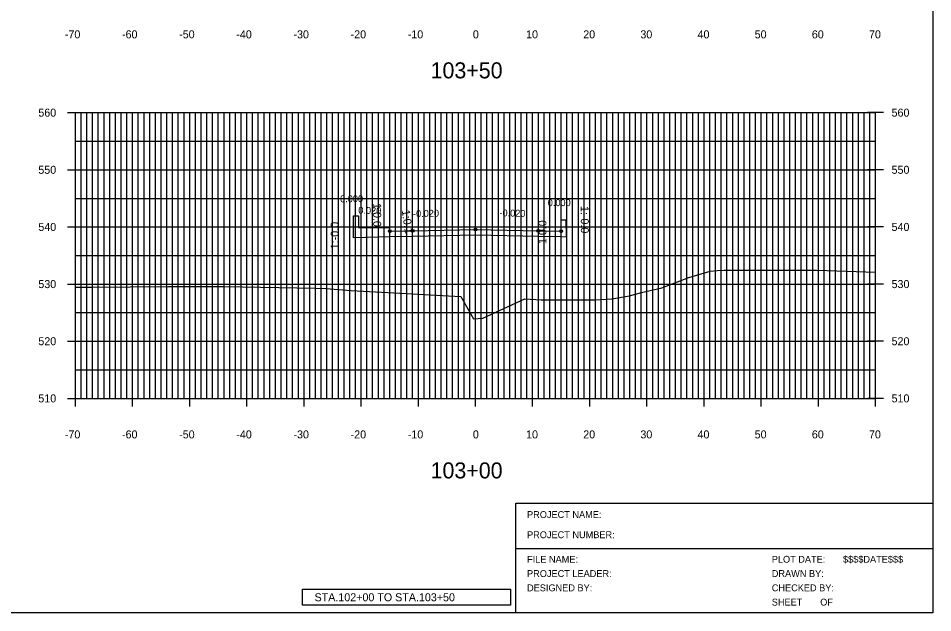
# Model space of a CAD drawing. Extents: x 1509063 to 1512863, y 401160 to 402918.
# Drawn here: x 1511622.7 to 1511782.7, y 402252.1 to 402356.1 of the extents above; entities that cross this region are included whole.
import ezdxf

# ---------------------------------------------------------------- set-up
doc = ezdxf.new("R2010")
doc.units = 0
for name, color, linetype in [('NBL1', 7, 'Continuous'), ('PET_P', 7, 'Continuous'), ('PRC', 7, 'Continuous'), ('PSP_P', 7, 'Continuous'), ('XAX_P', 7, 'Continuous'), ('XAXTIC_P', 7, 'Continuous'), ('XAXTXT_P_T', 7, 'Continuous'), ('XFRAME_P', 7, 'Continuous'), ('XGL_P', 7, 'Continuous'), ('XSL1_P', 7, 'Continuous'), ('XSL1_P_T', 7, 'Continuous'), ('XSL3_P', 7, 'Continuous'), ('XSLOG', 7, 'Continuous')]:
    doc.layers.add(name, color=color, linetype=linetype)

msp = doc.modelspace()

# ---------------------------------------------------------------- linework, layer by layer
at = {"layer": 'NBL1'}
for p, q in [((1511709.81, 402271.25), (1511782.73, 402271.25)), ((1511709.81, 402252.08), (1511709.81, 402271.25)), ((1511709.81, 402263.33), (1511782.73, 402263.33))]:
    msp.add_line(p, q, dxfattribs=at)
msp.add_lwpolyline([(1511782.73, 402252.08), (1511462.73, 402252.08), (1511462.73, 402462.08), (1511782.73, 402462.08)], close=True, dxfattribs=at)
at = {"layer": 'PET_P'}
for centre in [(1511691.73, 402318.9), (1511713.73, 402318.9)]:
    msp.add_circle(centre, 0.25, dxfattribs=at)
at = {"layer": 'PRC'}
msp.add_circle((1511702.73, 402319.12), 0.25, dxfattribs=at)
at = {"layer": 'PSP_P'}
for centre in [(1511687.73, 402318.82), (1511717.73, 402318.82)]:
    msp.add_circle(centre, 0.25, dxfattribs=at)
at = {"layer": 'XAX_P'}
for p, q in [((1511632.73, 402289.58), (1511632.73, 402339.58)), ((1511702.73, 402289.58), (1511702.73, 402339.58)), ((1511772.73, 402289.58), (1511772.73, 402339.58)), ((1511632.73, 402289.58), (1511772.73, 402289.58))]:
    msp.add_line(p, q, dxfattribs=at)
at = {"layer": 'XAXTIC_P'}
for p, q in [((1511631.33, 402339.58), (1511634.13, 402339.58)), ((1511701.33, 402339.58), (1511704.13, 402339.58)), ((1511774.13, 402339.58), (1511771.33, 402339.58)), ((1511631.33, 402329.58), (1511634.13, 402329.58)), ((1511701.33, 402329.58), (1511704.13, 402329.58)), ((1511774.13, 402329.58), (1511771.33, 402329.58)), ((1511631.33, 402319.58), (1511634.13, 402319.58)), ((1511701.33, 402319.58), (1511704.13, 402319.58)), ((1511774.13, 402319.58), (1511771.33, 402319.58)), ((1511631.33, 402309.58), (1511634.13, 402309.58)), ((1511701.33, 402309.58), (1511704.13, 402309.58)), ((1511774.13, 402309.58), (1511771.33, 402309.58)), ((1511631.33, 402299.58), (1511634.13, 402299.58)), ((1511701.33, 402299.58), (1511704.13, 402299.58)), ((1511774.13, 402299.58), (1511771.33, 402299.58)), ((1511632.73, 402288.18), (1511632.73, 402290.98)), ((1511642.73, 402288.18), (1511642.73, 402290.98)), ((1511652.73, 402288.18), (1511652.73, 402290.98)), ((1511662.73, 402288.18), (1511662.73, 402290.98)), ((1511672.73, 402288.18), (1511672.73, 402290.98)), ((1511682.73, 402288.18), (1511682.73, 402290.98)), ((1511692.73, 402288.18), (1511692.73, 402290.98)), ((1511702.73, 402288.18), (1511702.73, 402290.98)), ((1511712.73, 402288.18), (1511712.73, 402290.98)), ((1511722.73, 402288.18), (1511722.73, 402290.98)), ((1511732.73, 402288.18), (1511732.73, 402290.98)), ((1511742.73, 402288.18), (1511742.73, 402290.98)), ((1511752.73, 402288.18), (1511752.73, 402290.98)), ((1511762.73, 402288.18), (1511762.73, 402290.98)), ((1511772.73, 402288.18), (1511772.73, 402290.98)), ((1511631.33, 402289.58), (1511634.13, 402289.58)), ((1511701.33, 402289.58), (1511704.13, 402289.58)), ((1511774.13, 402289.58), (1511771.33, 402289.58))]:
    msp.add_line(p, q, dxfattribs=at)
at = {"layer": 'XFRAME_P'}
msp.add_lwpolyline([(1511672.43, 402256.18), (1511708.83, 402256.18), (1511708.83, 402253.38), (1511672.43, 402253.38)], close=True, dxfattribs=at)
at = {"layer": 'XGL_P'}
for p, q in [((1511632.73, 402339.58), (1511772.73, 402339.58)), ((1511632.73, 402289.58), (1511632.73, 402339.58)), ((1511633.73, 402289.58), (1511633.73, 402339.58)), ((1511634.73, 402289.58), (1511634.73, 402339.58)), ((1511635.73, 402289.58), (1511635.73, 402339.58)), ((1511636.73, 402289.58), (1511636.73, 402339.58)), ((1511637.73, 402289.58), (1511637.73, 402339.58)), ((1511638.73, 402289.58), (1511638.73, 402339.58)), ((1511639.73, 402289.58), (1511639.73, 402339.58)), ((1511640.73, 402289.58), (1511640.73, 402339.58)), ((1511641.73, 402289.58), (1511641.73, 402339.58)), ((1511642.73, 402289.58), (1511642.73, 402339.58)), ((1511643.73, 402289.58), (1511643.73, 402339.58)), ((1511644.73, 402289.58), (1511644.73, 402339.58)), ((1511645.73, 402289.58), (1511645.73, 402339.58)), ((1511646.73, 402289.58), (1511646.73, 402339.58)), ((1511647.73, 402289.58), (1511647.73, 402339.58)), ((1511648.73, 402289.58), (1511648.73, 402339.58)), ((1511649.73, 402289.58), (1511649.73, 402339.58)), ((1511650.73, 402289.58), (1511650.73, 402339.58)), ((1511651.73, 402289.58), (1511651.73, 402339.58)), ((1511652.73, 402289.58), (1511652.73, 402339.58)), ((1511653.73, 402289.58), (1511653.73, 402339.58)), ((1511654.73, 402289.58), (1511654.73, 402339.58)), ((1511655.73, 402289.58), (1511655.73, 402339.58)), ((1511656.73, 402289.58), (1511656.73, 402339.58)), ((1511657.73, 402289.58), (1511657.73, 402339.58)), ((1511658.73, 402289.58), (1511658.73, 402339.58)), ((1511659.73, 402289.58), (1511659.73, 402339.58)), ((1511660.73, 402289.58), (1511660.73, 402339.58)), ((1511661.73, 402289.58), (1511661.73, 402339.58)), ((1511662.73, 402289.58), (1511662.73, 402339.58)), ((1511663.73, 402289.58), (1511663.73, 402339.58)), ((1511664.73, 402289.58), (1511664.73, 402339.58)), ((1511665.73, 402289.58), (1511665.73, 402339.58)), ((1511666.73, 402289.58), (1511666.73, 402339.58)), ((1511667.73, 402289.58), (1511667.73, 402339.58)), ((1511668.73, 402289.58), (1511668.73, 402339.58)), ((1511669.73, 402289.58), (1511669.73, 402339.58)), ((1511670.73, 402289.58), (1511670.73, 402339.58)), ((1511671.73, 402289.58), (1511671.73, 402339.58)), ((1511672.73, 402289.58), (1511672.73, 402339.58)), ((1511673.73, 402289.58), (1511673.73, 402339.58)), ((1511674.73, 402289.58), (1511674.73, 402339.58)), ((1511675.73, 402289.58), (1511675.73, 402339.58)), ((1511676.73, 402289.58), (1511676.73, 402339.58)), ((1511677.73, 402289.58), (1511677.73, 402339.58)), ((1511678.73, 402289.58), (1511678.73, 402339.58)), ((1511679.73, 402289.58), (1511679.73, 402339.58)), ((1511680.73, 402289.58), (1511680.73, 402339.58)), ((1511681.73, 402289.58), (1511681.73, 402339.58)), ((1511682.73, 402289.58), (1511682.73, 402339.58)), ((1511683.73, 402289.58), (1511683.73, 402339.58)), ((1511684.73, 402289.58), (1511684.73, 402339.58)), ((1511685.73, 402289.58), (1511685.73, 402339.58)), ((1511686.73, 402289.58), (1511686.73, 402339.58)), ((1511687.73, 402289.58), (1511687.73, 402339.58)), ((1511688.73, 402289.58), (1511688.73, 402339.58)), ((1511689.73, 402289.58), (1511689.73, 402339.58)), ((1511690.73, 402289.58), (1511690.73, 402339.58)), ((1511691.73, 402289.58), (1511691.73, 402339.58)), ((1511692.73, 402289.58), (1511692.73, 402339.58)), ((1511693.73, 402289.58), (1511693.73, 402339.58)), ((1511694.73, 402289.58), (1511694.73, 402339.58)), ((1511695.73, 402289.58), (1511695.73, 402339.58)), ((1511696.73, 402289.58), (1511696.73, 402339.58)), ((1511697.73, 402289.58), (1511697.73, 402339.58)), ((1511698.73, 402289.58), (1511698.73, 402339.58)), ((1511699.73, 402289.58), (1511699.73, 402339.58)), ((1511700.73, 402289.58), (1511700.73, 402339.58)), ((1511701.73, 402289.58), (1511701.73, 402339.58)), ((1511702.73, 402289.58), (1511702.73, 402339.58)), ((1511703.73, 402289.58), (1511703.73, 402339.58)), ((1511704.73, 402289.58), (1511704.73, 402339.58)), ((1511705.73, 402289.58), (1511705.73, 402339.58)), ((1511706.73, 402289.58), (1511706.73, 402339.58)), ((1511707.73, 402289.58), (1511707.73, 402339.58)), ((1511708.73, 402289.58), (1511708.73, 402339.58)), ((1511709.73, 402289.58), (1511709.73, 402339.58)), ((1511710.73, 402289.58), (1511710.73, 402339.58)), ((1511711.73, 402289.58), (1511711.73, 402339.58)), ((1511712.73, 402289.58), (1511712.73, 402339.58)), ((1511713.73, 402289.58), (1511713.73, 402339.58)), ((1511714.73, 402289.58), (1511714.73, 402339.58)), ((1511715.73, 402289.58), (1511715.73, 402339.58)), ((1511716.73, 402289.58), (1511716.73, 402339.58)), ((1511717.73, 402289.58), (1511717.73, 402339.58)), ((1511718.73, 402289.58), (1511718.73, 402339.58)), ((1511719.73, 402289.58), (1511719.73, 402339.58)), ((1511720.73, 402289.58), (1511720.73, 402339.58)), ((1511721.73, 402289.58), (1511721.73, 402339.58)), ((1511722.73, 402289.58), (1511722.73, 402339.58)), ((1511723.73, 402289.58), (1511723.73, 402339.58)), ((1511724.73, 402289.58), (1511724.73, 402339.58)), ((1511725.73, 402289.58), (1511725.73, 402339.58)), ((1511726.73, 402289.58), (1511726.73, 402339.58)), ((1511727.73, 402289.58), (1511727.73, 402339.58)), ((1511728.73, 402289.58), (1511728.73, 402339.58)), ((1511729.73, 402289.58), (1511729.73, 402339.58)), ((1511730.73, 402289.58), (1511730.73, 402339.58)), ((1511731.73, 402289.58), (1511731.73, 402339.58)), ((1511732.73, 402289.58), (1511732.73, 402339.58)), ((1511733.73, 402289.58), (1511733.73, 402339.58)), ((1511734.73, 402289.58), (1511734.73, 402339.58)), ((1511735.73, 402289.58), (1511735.73, 402339.58)), ((1511736.73, 402289.58), (1511736.73, 402339.58)), ((1511737.73, 402289.58), (1511737.73, 402339.58)), ((1511738.73, 402289.58), (1511738.73, 402339.58)), ((1511739.73, 402289.58), (1511739.73, 402339.58)), ((1511740.73, 402289.58), (1511740.73, 402339.58)), ((1511741.73, 402289.58), (1511741.73, 402339.58)), ((1511742.73, 402289.58), (1511742.73, 402339.58)), ((1511743.73, 402289.58), (1511743.73, 402339.58)), ((1511744.73, 402289.58), (1511744.73, 402339.58)), ((1511745.73, 402289.58), (1511745.73, 402339.58)), ((1511746.73, 402289.58), (1511746.73, 402339.58)), ((1511747.73, 402289.58), (1511747.73, 402339.58)), ((1511748.73, 402289.58), (1511748.73, 402339.58)), ((1511749.73, 402289.58), (1511749.73, 402339.58)), ((1511750.73, 402289.58), (1511750.73, 402339.58)), ((1511751.73, 402289.58), (1511751.73, 402339.58)), ((1511752.73, 402289.58), (1511752.73, 402339.58)), ((1511753.73, 402289.58), (1511753.73, 402339.58)), ((1511754.73, 402289.58), (1511754.73, 402339.58)), ((1511755.73, 402289.58), (1511755.73, 402339.58)), ((1511756.73, 402289.58), (1511756.73, 402339.58)), ((1511757.73, 402289.58), (1511757.73, 402339.58)), ((1511758.73, 402289.58), (1511758.73, 402339.58)), ((1511759.73, 402289.58), (1511759.73, 402339.58)), ((1511760.73, 402289.58), (1511760.73, 402339.58)), ((1511761.73, 402289.58), (1511761.73, 402339.58)), ((1511762.73, 402289.58), (1511762.73, 402339.58)), ((1511763.73, 402289.58), (1511763.73, 402339.58)), ((1511764.73, 402289.58), (1511764.73, 402339.58)), ((1511765.73, 402289.58), (1511765.73, 402339.58)), ((1511766.73, 402289.58), (1511766.73, 402339.58)), ((1511767.73, 402289.58), (1511767.73, 402339.58)), ((1511768.73, 402289.58), (1511768.73, 402339.58)), ((1511769.73, 402289.58), (1511769.73, 402339.58)), ((1511770.73, 402289.58), (1511770.73, 402339.58)), ((1511771.73, 402289.58), (1511771.73, 402339.58)), ((1511772.73, 402289.58), (1511772.73, 402339.58)), ((1511632.73, 402334.58), (1511772.73, 402334.58)), ((1511632.73, 402329.58), (1511772.73, 402329.58)), ((1511632.73, 402324.58), (1511772.73, 402324.58)), ((1511632.73, 402319.58), (1511772.73, 402319.58)), ((1511632.73, 402314.58), (1511772.73, 402314.58)), ((1511632.73, 402309.58), (1511772.73, 402309.58)), ((1511632.73, 402304.58), (1511772.73, 402304.58)), ((1511632.73, 402299.58), (1511772.73, 402299.58)), ((1511632.73, 402294.58), (1511772.73, 402294.58)), ((1511632.73, 402289.58), (1511772.73, 402289.58))]:
    msp.add_line(p, q, dxfattribs=at)
at = {"layer": 'XSL1_P'}
msp.add_lwpolyline([(1511681.39, 402317.69), (1511681.4, 402321.51), (1511682.23, 402321.51), (1511682.23, 402319.51), (1511687.65, 402319.4), (1511687.73, 402318.82), (1511691.73, 402318.9), (1511702.73, 402319.12), (1511713.73, 402318.9), (1511717.73, 402318.82), (1511717.73, 402320.82), (1511718.56, 402320.82), (1511718.57, 402317.8)], dxfattribs=at)
at = {"layer": 'XSL3_P'}
msp.add_lwpolyline([(1511691.73, 402317.9), (1511687.73, 402317.82), (1511681.39, 402317.69), (1511681.4, 402321.51), (1511682.23, 402321.51), (1511682.23, 402319.51), (1511687.65, 402319.4), (1511687.73, 402318.82), (1511691.73, 402318.9), (1511702.72, 402319.12), (1511713.73, 402318.9), (1511717.73, 402318.82), (1511717.73, 402320.82), (1511718.56, 402320.82), (1511718.57, 402317.8), (1511717.73, 402317.82), (1511713.73, 402317.9), (1511702.72, 402318.12)], close=True, dxfattribs=at)
at = {"layer": 'XSLOG'}
msp.add_lwpolyline([(1511632.73, 402309.03), (1511635.6, 402309.03), (1511648.99, 402309.18), (1511658.8, 402309.18), (1511674.6, 402308.89), (1511676.52, 402308.81), (1511680.95, 402308.47), (1511700.18, 402307.39), (1511702.36, 402303.48), (1511704.03, 402303.6), (1511711.36, 402306.98), (1511714.21, 402306.85), (1511723.78, 402306.8), (1511726.56, 402307), (1511729.68, 402307.53), (1511731.8, 402308.11), (1511735.35, 402308.95), (1511740.07, 402310.76), (1511743.78, 402311.82), (1511745.03, 402311.98), (1511746.21, 402312.01), (1511749.2, 402312.04), (1511751.37, 402312.03), (1511751.69, 402312.02), (1511760.78, 402312.03), (1511762.38, 402312.04), (1511764.28, 402311.98), (1511772.73, 402311.67)], dxfattribs=at)

# ---------------------------------------------------------------- texts
at = {"layer": 'NBL1'}
for s, p in [('PROJECT NAME:', (1511711.75, 402268.65)), ('PROJECT NUMBER:', (1511711.75, 402265.12)), ('FILE NAME:', (1511711.75, 402260.83)), ('PLOT DATE:', (1511754.57, 402260.83)), ('$$$$DATE$$$', (1511767.03, 402260.83)), ('PROJECT LEADER:', (1511711.75, 402258.33)), ('DRAWN BY:', (1511754.57, 402258.33)), ('DESIGNED BY:', (1511711.75, 402255.83)), ('CHECKED BY:', (1511754.57, 402255.83)), ('SHEET       OF', (1511754.57, 402253.33))]:
    msp.add_text(s, height=1.2, rotation=360, dxfattribs=at).set_placement(p)
at = {"layer": 'XAXTXT_P_T'}
for s, height, p in [('-70', 1.4, (1511630.88, 402352.58)), ('-60', 1.4, (1511640.88, 402352.58)), ('-50', 1.4, (1511650.88, 402352.58)), ('-40', 1.4, (1511660.88, 402352.58)), ('-30', 1.4, (1511670.88, 402352.58)), ('-20', 1.4, (1511680.88, 402352.58)), ('-10', 1.4, (1511690.88, 402352.58)), ('0', 1.4, (1511702.27, 402352.58)), ('10', 1.4, (1511711.58, 402352.58)), ('20', 1.4, (1511721.58, 402352.58)), ('30', 1.4, (1511731.58, 402352.58)), ('40', 1.4, (1511741.58, 402352.58)), ('50', 1.4, (1511751.58, 402352.58)), ('60', 1.4, (1511761.58, 402352.58)), ('70', 1.4, (1511771.58, 402352.58)), ('103+50', 2.8, (1511694.87, 402345.58)), ('560', 1.4, (1511626.24, 402338.88)), ('560', 1.4, (1511775.53, 402338.88)), ('550', 1.4, (1511626.24, 402328.88)), ('550', 1.4, (1511775.53, 402328.88)), ('540', 1.4, (1511626.24, 402318.88)), ('540', 1.4, (1511775.53, 402318.88)), ('530', 1.4, (1511626.24, 402308.88)), ('530', 1.4, (1511775.53, 402308.88)), ('520', 1.4, (1511626.24, 402298.88)), ('520', 1.4, (1511775.53, 402298.88)), ('510', 1.4, (1511626.24, 402288.88)), ('510', 1.4, (1511775.53, 402288.88)), ('-70', 1.4, (1511630.88, 402282.58)), ('-60', 1.4, (1511640.88, 402282.58)), ('-50', 1.4, (1511650.88, 402282.58)), ('-40', 1.4, (1511660.88, 402282.58)), ('-30', 1.4, (1511670.88, 402282.58)), ('-20', 1.4, (1511680.88, 402282.58)), ('-10', 1.4, (1511690.88, 402282.58)), ('0', 1.4, (1511702.27, 402282.58)), ('10', 1.4, (1511711.58, 402282.58)), ('20', 1.4, (1511721.58, 402282.58)), ('30', 1.4, (1511731.58, 402282.58)), ('40', 1.4, (1511741.58, 402282.58)), ('50', 1.4, (1511751.58, 402282.58)), ('60', 1.4, (1511761.58, 402282.58)), ('70', 1.4, (1511771.58, 402282.58)), ('103+00', 2.8, (1511694.87, 402275.58))]:
    msp.add_text(s, height=height, dxfattribs=at).set_placement(p)
at = {"layer": 'XFRAME_P'}
msp.add_text('STA.102+00 TO STA.103+50', height=1.4, dxfattribs=at).set_placement((1511674.57, 402254.08))
at = {"layer": 'XSL1_P_T'}
for s, height, rotation, p in [('0.000', 1.2, 360, (1511679.04, 402323.91)), ('0.000', 1.2, 360, (1511679.04, 402323.91)), ('1:0.0', 1.4, 270.0286, (1511684.83, 402323.75)), ('1:0.0', 1.4, 270.0286, (1511684.83, 402323.75)), ('0.000', 1.2, 360, (1511715.37, 402323.22)), ('0.000', 1.2, 360, (1511715.37, 402323.22)), ('0.020', 1.2, 358.8542, (1511682.21, 402321.91)), ('0.020', 1.2, 358.8542, (1511682.21, 402321.91)), ('1:0.1', 1.4, 278.1301, (1511689.83, 402322.46)), ('1:0.1', 1.4, 278.1301, (1511689.83, 402322.46)), ('-0.020', 1.2, 1.1458, (1511691.81, 402321.3)), ('-0.020', 1.2, 1.1458, (1511691.81, 402321.3)), ('-0.020', 1.2, 1.1458, (1511691.81, 402321.3)), ('-0.020', 1.2, 358.8542, (1511706.91, 402321.44)), ('-0.020', 1.2, 358.8542, (1511706.91, 402321.44)), ('-0.020', 1.2, 358.8542, (1511706.91, 402321.44)), ('1:-0.0', 1.4, 270.1899, (1511721.15, 402323.25)), ('1:-0.0', 1.4, 270.1899, (1511721.15, 402323.25)), ('1:-0.0', 1.4, 89.85, (1511678.78, 402315.68)), ('1:-0.0', 1.4, 89.85, (1511678.78, 402315.68)), ('1:0.0', 1.4, 89.9714, (1511715.13, 402316.58)), ('1:0.0', 1.4, 89.9714, (1511715.13, 402316.58))]:
    msp.add_text(s, height=height, rotation=rotation, dxfattribs=at).set_placement(p)

doc.saveas('drawing.dxf')
